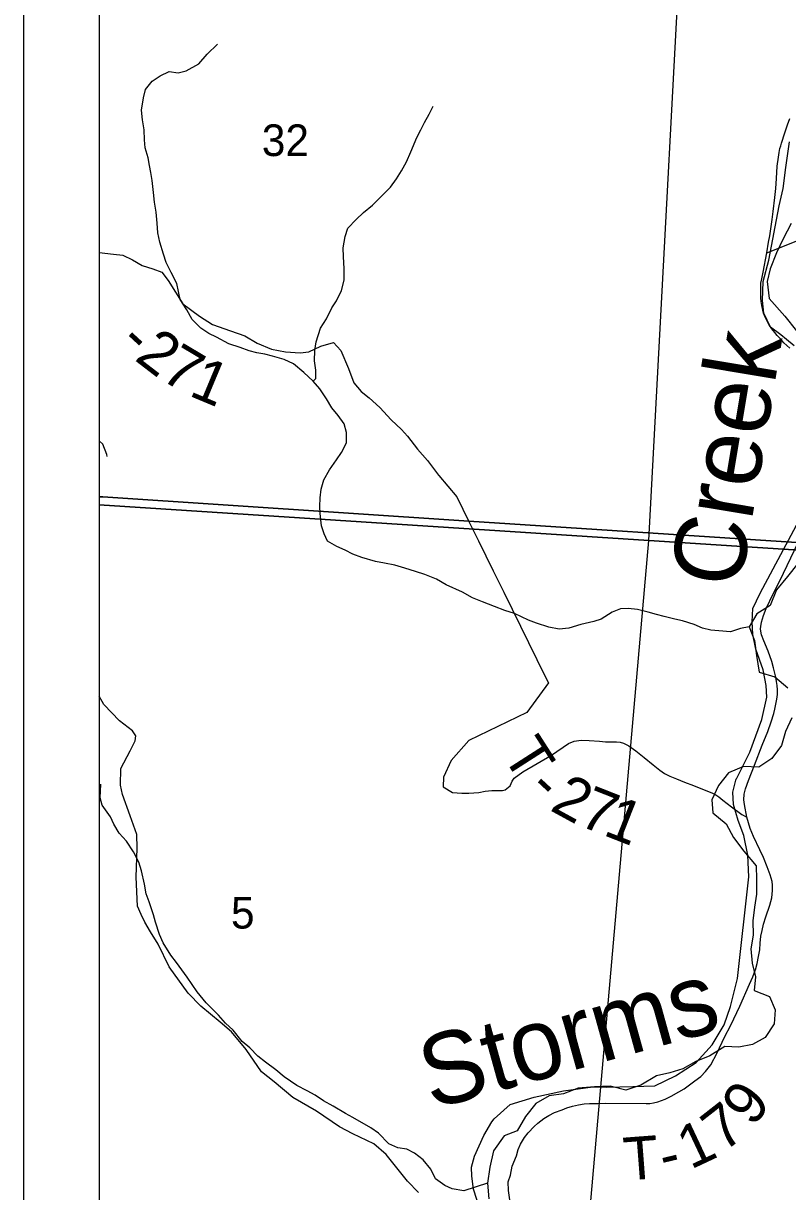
# Model space of a CAD drawing. Extents: x 0 to 34, y 0 to 22.
# Drawn here: x 2 to 3.01, y 18.721 to 20.265 of the extents above; entities that cross this region are included whole.
import ezdxf

# ---------------------------------------------------------------- set-up
doc = ezdxf.new("R2010")
doc.units = 0
for name, color, linetype in [('GM_X_Corporation', 7, 'Continuous'), ('GM_X_County_Road', 7, 'Continuous'), ('GM_X_Minor_River', 7, 'Continuous'), ('GM_X_Minor_River_Text', 7, 'Continuous'), ('GM_X_Rail_Line', 7, 'Continuous'), ('GM_X_Section_Text', 7, 'Continuous'), ('GM_X_Township_Road', 7, 'Continuous'), ('GM_X_Township_Road_Text', 7, 'Continuous'), ('SH_Data', 7, 'Continuous')]:
    doc.layers.add(name, color=color, linetype=linetype)

msp = doc.modelspace()

# ---------------------------------------------------------------- linework, layer by layer
at = {"layer": 'GM_X_Corporation'}
for points in [[(3.3441, 14.1), (8.9, 14.1), (8.9, 20.9), (2.1, 20.9), (2.1, 16.1353), (2.1457, 16.065), (2.3447, 15.6926), (2.4297, 15.5215), (2.465, 15.4504), (2.4884, 15.4033), (2.5769, 15.2135), (2.7849, 14.8403), (2.8931, 14.6544), (3.0297, 14.4867), (3.1386, 14.3654), (3.228, 14.2415)], [(6.9348, 20.9), (2.1, 20.9), (2.1, 19.6396), (2.105, 19.6393), (2.5886, 19.6074), (3.0215, 19.5789), (3.8201, 19.5262), (3.8692, 19.5228), (4.8375, 19.4557), (5.0201, 19.4401), (5.6539, 19.3859), (5.9419, 19.3649), (6.5423, 19.3229), (6.824, 19.3005), (6.835, 19.4037), (6.8961, 20.3303), (6.9032, 20.4198)], [(2.1, 20.6488), (2.1, 19.629), (2.8266, 19.5815), (2.8805, 20.5967)], [(3.8795, 20.5363), (3.8179, 19.5177), (2.8266, 19.5815), (2.8805, 20.5967)], [(2.1, 19.629), (2.1, 18.5966), (2.7366, 18.558), (2.8266, 19.5815)], [(2.8266, 19.5815), (3.8179, 19.5177), (3.742, 18.4953), (2.7366, 18.558)]]:
    msp.add_lwpolyline(points, close=True, dxfattribs=at)
msp.add_lwpolyline([(6.7043, 17.4985), (6.7536, 18.2991), (6.7629, 18.3924), (6.7876, 18.7583), (6.824, 19.3005), (6.5423, 19.3229), (5.9419, 19.3649), (5.6539, 19.3859), (5.0201, 19.4401), (4.8375, 19.4557), (3.8692, 19.5228), (3.8201, 19.5262), (3.0215, 19.5789), (2.5886, 19.6074), (2.105, 19.6393), (2.1, 19.6396), (2.1, 16.1353)], dxfattribs=at)
at = {"layer": 'GM_X_County_Road'}
for points in [[(2.1107, 19.6926), (2.1105, 19.6955), (2.1049, 19.7092), (2.1, 19.7134)], [(2.5221, 18.7197), (2.5078, 18.7347), (2.4796, 18.7702), (2.4633, 18.7839), (2.4354, 18.7974), (2.4176, 18.8066), (2.3874, 18.8273), (2.356, 18.8454), (2.3315, 18.866), (2.3145, 18.8794), (2.2942, 18.9088), (2.2751, 18.9321), (2.26, 18.9451), (2.2343, 18.9662), (2.2177, 18.9834), (2.1926, 19.0181), (2.178, 19.0482), (2.1682, 19.0642), (2.1607, 19.0772), (2.1555, 19.0871), (2.1506, 19.0985), (2.149, 19.1365), (2.1503, 19.1749), (2.1501, 19.1931), (2.1411, 19.2178), (2.1311, 19.246), (2.1285, 19.2582), (2.129, 19.2802), (2.1409, 19.3037), (2.1479, 19.3169), (2.1487, 19.3234), (2.1441, 19.3299), (2.1268, 19.3433), (2.1061, 19.365), (2.1, 19.3757)]]:
    msp.add_lwpolyline(points, dxfattribs=at)
at = {"layer": 'GM_X_Minor_River'}
for points in [[(2.2045, 20.2001), (2.2151, 20.2024), (2.2317, 20.2119), (2.2427, 20.2244), (2.2566, 20.2377)], [(2.959, 19.4675), (2.9475, 19.4655), (2.9343, 19.461), (2.9191, 19.4621), (2.9082, 19.4632), (2.8972, 19.4659), (2.8863, 19.4708), (2.8711, 19.4757), (2.8609, 19.4776), (2.8469, 19.481), (2.8364, 19.484), (2.8254, 19.4871), (2.8114, 19.4905), (2.7993, 19.492), (2.7891, 19.4912), (2.7781, 19.487), (2.7634, 19.4779), (2.7536, 19.4745), (2.7366, 19.4707), (2.7207, 19.4658), (2.7082, 19.4646), (2.6942, 19.4669), (2.678, 19.4726), (2.6674, 19.4763), (2.6489, 19.4851), (2.6364, 19.4892), (2.6224, 19.4945), (2.6069, 19.5006), (2.5933, 19.5059), (2.5801, 19.5135), (2.5585, 19.5229), (2.5461, 19.5305), (2.5306, 19.5366), (2.5181, 19.5407), (2.5041, 19.5449), (2.4909, 19.5491), (2.4773, 19.5517), (2.4655, 19.554), (2.4474, 19.5593), (2.4353, 19.5638), (2.4251, 19.5687), (2.4141, 19.5737), (2.402, 19.5809), (2.3975, 19.5907), (2.3941, 19.601), (2.3922, 19.6173), (2.3918, 19.6268), (2.3922, 19.6381), (2.3937, 19.6495), (2.3971, 19.6617), (2.4047, 19.6753), (2.4138, 19.6882), (2.4202, 19.6981), (2.427, 19.7106), (2.427, 19.7243), (2.424, 19.736), (2.4161, 19.747), (2.4078, 19.7572), (2.4006, 19.769), (2.3919, 19.7823), (2.3828, 19.7925), (2.3707, 19.8039), (2.3571, 19.8152), (2.3446, 19.8209), (2.3291, 19.8255), (2.3189, 19.8281), (2.3083, 19.8296), (2.2985, 19.8323), (2.2864, 19.8368), (2.2713, 19.8417), (2.2551, 19.8505), (2.2452, 19.8554), (2.2346, 19.8626), (2.2229, 19.874), (2.2161, 19.8865), (2.2071, 19.9005), (2.2029, 19.9214), (2.1953, 19.9358), (2.1889, 19.9494), (2.1851, 19.96), (2.1802, 19.9763), (2.1776, 19.9885), (2.1768, 20.001), (2.1753, 20.0158), (2.1734, 20.0291), (2.1719, 20.0416), (2.17, 20.0575), (2.1685, 20.0681), (2.1666, 20.0776), (2.1648, 20.0875), (2.161, 20.1007), (2.1602, 20.1113), (2.1595, 20.1246), (2.1576, 20.1379), (2.1561, 20.1508), (2.1587, 20.1671), (2.1614, 20.1777), (2.1704, 20.1887), (2.1807, 20.1959), (2.1928, 20.2016), (2.2045, 20.2001)], [(2.3828, 19.7925), (2.3866, 19.7959), (2.3866, 19.8069), (2.3847, 19.8194), (2.3851, 19.8327), (2.387, 19.8445), (2.3927, 19.8623), (2.4006, 19.8748), (2.4078, 19.8892), (2.4138, 19.8987), (2.4203, 19.9124), (2.424, 19.926), (2.4237, 19.9412), (2.4229, 19.9568), (2.4225, 19.9685), (2.4252, 19.9837), (2.4286, 19.9947), (2.4396, 20.0061), (2.4494, 20.0152), (2.4615, 20.0251), (2.4853, 20.049), (2.4932, 20.0596), (2.4997, 20.0706), (2.5061, 20.0824), (2.5118, 20.0956), (2.5197, 20.1146), (2.525, 20.1245), (2.5299, 20.1343), (2.5364, 20.1453), (2.5417, 20.156)], [(3.0147, 20.0007), (3.0041, 19.9806), (2.9953, 19.9619), (2.987, 19.941), (2.9828, 19.9239), (2.9857, 19.9015), (3.0061, 19.8783), (3.0216, 19.8588)], [(3.0235, 19.5512), (3.0099, 19.5341), (2.9954, 19.5166), (2.9867, 19.4957), (2.9692, 19.4847), (2.959, 19.4675), (2.9661, 19.4497), (2.9687, 19.4295), (2.9721, 19.4078), (2.9929, 19.4013), (3.0103, 19.3869)], [(3.0155, 19.3473), (3.0071, 19.3294), (3.0018, 19.3108), (2.9889, 19.2933), (2.9718, 19.2819), (2.9517, 19.2831), (2.9317, 19.2747), (2.9187, 19.2576), (2.9096, 19.239), (2.9111, 19.2215), (2.9285, 19.207), (2.9383, 19.1891), (2.9519, 19.1709), (2.9685, 19.1518), (2.9688, 19.134), (2.9688, 19.1142), (2.9661, 19.0971), (2.9638, 19.0788), (2.9645, 19.0598), (2.9614, 19.0419), (2.9632, 19.0229), (2.9674, 19.005), (2.9658, 18.9867), (2.9859, 18.9787), (2.9934, 18.9612), (2.9922, 18.9426), (2.9804, 18.9247)], [(2.6132, 18.7321), (2.5822, 18.722), (2.5667, 18.7247), (2.5568, 18.7292), (2.5448, 18.738), (2.5383, 18.7505), (2.5285, 18.763), (2.5168, 18.7717), (2.5066, 18.777), (2.4949, 18.7789), (2.4828, 18.7842), (2.4692, 18.7982), (2.4593, 18.8054), (2.4355, 18.8187), (2.4257, 18.824), (2.4094, 18.8339), (2.3966, 18.8411), (2.3856, 18.8483), (2.3751, 18.8543), (2.3614, 18.8612), (2.3448, 18.8725), (2.3335, 18.882), (2.3199, 18.8919), (2.31, 18.8998), (2.2991, 18.9108), (2.2893, 18.9192), (2.2772, 18.9343), (2.2673, 18.9438), (2.2579, 18.9544), (2.2416, 18.9707), (2.2295, 18.9852), (2.2163, 19.0045), (2.2023, 19.0238), (2.1948, 19.0337), (2.1846, 19.05), (2.1797, 19.061), (2.1744, 19.0773), (2.1721, 19.0868), (2.1661, 19.1042), (2.1623, 19.1145), (2.16, 19.1274), (2.1562, 19.1448), (2.1525, 19.1566), (2.1453, 19.1699), (2.1362, 19.1843), (2.1264, 19.1949), (2.1196, 19.2067), (2.1151, 19.2165), (2.1041, 19.2317), (2.1015, 19.2415), (2.1022, 19.2594)], [(2.9804, 18.9247), (2.9634, 18.9152), (2.9456, 18.9118), (2.927, 18.9126), (2.9073, 18.9004), (2.8884, 18.8928), (2.8713, 18.8833), (2.8543, 18.878), (2.8368, 18.8742), (2.816, 18.8617), (2.7963, 18.8549), (2.7755, 18.8602), (2.7547, 18.8595), (2.7331, 18.8576), (2.7138, 18.8504), (2.6948, 18.8477), (2.677, 18.8375), (2.6633, 18.8203), (2.6523, 18.8013), (2.6353, 18.7945), (2.6212, 18.7747), (2.6166, 18.7534), (2.6132, 18.7321), (2.615, 18.7116)]]:
    msp.add_lwpolyline(points, dxfattribs=at)
at = {"layer": 'GM_X_Rail_Line'}
for points in [[(3.0185, 19.8389), (3.0085, 19.8476), (3.0009, 19.8537), (2.9873, 19.8639), (2.9785, 19.8824), (2.9769, 19.8989), (2.9777, 19.9242), (2.9849, 19.9524), (2.9986, 20.024), (3.0042, 20.0469), (3.0073, 20.0748), (3.0122, 20.1085)], [(2.6037, 18.697), (2.5949, 18.7243), (2.5928, 18.7415), (2.5922, 18.7534), (2.5963, 18.7678), (2.6085, 18.7949), (2.6192, 18.813), (2.622, 18.8173), (2.6431, 18.8359), (2.6751, 18.8459), (2.7137, 18.8542), (2.7524, 18.8593), (2.7708, 18.8588), (2.8053, 18.8598), (2.8345, 18.8609), (2.8618, 18.8738), (2.8892, 18.8915), (2.9101, 18.9149), (2.9262, 18.9414), (2.9342, 18.9656), (2.9435, 19.0028), (2.9587, 19.1369), (2.9573, 19.1659), (2.9522, 19.1918), (2.9444, 19.2115), (2.9382, 19.2329), (2.9377, 19.2488), (2.9417, 19.2665), (2.9423, 19.2667), (2.9599, 19.3018), (2.9759, 19.345), (2.9825, 19.3745), (2.9817, 19.3898), (2.9777, 19.4108), (2.968, 19.4381), (2.964, 19.4574), (2.9632, 19.4743), (2.964, 19.492), (2.9736, 19.5122), (3.0452, 19.6466)]]:
    msp.add_lwpolyline(points, dxfattribs=at)
at = {"layer": 'GM_X_Township_Road'}
msp.add_line((2.6349, 19.5133), (2.6897, 19.4018), dxfattribs=at)
for points in [[(3.0126, 19.836), (3.005, 19.8431), (3.0004, 19.8482), (2.9961, 19.8526), (2.9928, 19.8565), (2.989, 19.8613), (2.986, 19.8658), (2.9831, 19.8707), (2.98, 19.8769), (2.9779, 19.8824), (2.9756, 19.8922), (2.9748, 19.8975), (2.9745, 19.9027), (2.9743, 19.9064), (2.9743, 19.9103), (2.9743, 19.915), (2.9747, 19.9217), (2.9756, 19.9276), (2.9774, 19.9366), (2.9823, 19.9621), (2.9848, 19.9762), (2.9862, 19.9845), (2.9893, 20.0059), (2.9908, 20.0167), (2.9929, 20.0351), (2.9942, 20.0469), (2.9951, 20.0602), (2.9962, 20.0764), (2.9977, 20.0886), (2.9986, 20.0948), (2.9998, 20.0997), (3.0007, 20.1034), (3.0017, 20.1071), (3.006, 20.1205), (3.0098, 20.1312), (3.0129, 20.1395)], [(2.9823, 19.9621), (3.107, 20.0118), (3.2438, 20.0434), (3.2996, 20.0612), (3.3426, 20.0749), (3.3797, 20.0723), (3.3816, 20.0722)], [(2.1, 19.9623), (2.1191, 19.9604), (2.1313, 19.9589), (2.144, 19.9527), (2.157, 19.9451), (2.1712, 19.9409), (2.1831, 19.9366), (2.1915, 19.9255), (2.2108, 19.8946), (2.2327, 19.8781), (2.2497, 19.8674), (2.2739, 19.8589), (2.2928, 19.8523), (2.3091, 19.8424), (2.328, 19.8347), (2.3465, 19.8311), (2.3659, 19.8299), (2.3772, 19.8313), (2.3932, 19.8388), (2.4099, 19.8436), (2.4197, 19.833), (2.4298, 19.809), (2.4365, 19.7903), (2.4463, 19.7785), (2.4569, 19.7704), (2.4712, 19.7574), (2.4859, 19.741), (2.4998, 19.7284), (2.5077, 19.7196), (2.5209, 19.7025), (2.5341, 19.6876), (2.5484, 19.6681), (2.549, 19.6674), (2.5728, 19.6395), (2.5888, 19.6069), (2.6014, 19.5813), (2.6209, 19.5417), (2.6349, 19.5133)], [(3.0095, 19.5488), (3.0234, 19.5783)], [(2.6427, 18.7102), (2.6409, 18.7224), (2.6407, 18.734), (2.6436, 18.7428), (2.6459, 18.7544), (2.6515, 18.7684), (2.6538, 18.7764), (2.6568, 18.7838), (2.6623, 18.7926), (2.6671, 18.7985), (2.6748, 18.8069), (2.68, 18.8116), (2.6876, 18.8174), (2.6944, 18.8215), (2.7017, 18.8254), (2.7118, 18.8292), (2.7181, 18.8315), (2.7255, 18.8338), (2.7335, 18.8356), (2.7412, 18.8368), (2.7479, 18.8374), (2.7591, 18.8376), (2.7692, 18.8377), (2.8229, 18.8373), (2.8277, 18.8375), (2.8325, 18.8384), (2.8384, 18.8397), (2.8479, 18.8431), (2.8558, 18.8473), (2.866, 18.8529), (2.8731, 18.8569), (2.8872, 18.8672), (2.8952, 18.8732), (2.9014, 18.8798), (2.9084, 18.8887), (2.9166, 18.9042), (2.9266, 18.925), (2.9348, 18.941), (2.9467, 18.9661), (2.9597, 18.9952), (2.9638, 19.0048), (2.9671, 19.0133), (2.9674, 19.0142), (2.9695, 19.0224), (2.9715, 19.0319), (2.9732, 19.0407), (2.9735, 19.0492), (2.9747, 19.0585), (2.9761, 19.0662), (2.9779, 19.0746), (2.9813, 19.0843), (2.9864, 19.0997), (2.9891, 19.1092), (2.99, 19.1188), (2.9901, 19.126), (2.9894, 19.1311), (2.9867, 19.1396), (2.9827, 19.1505), (2.9778, 19.1624), (2.9733, 19.1729), (2.965, 19.1903), (2.9606, 19.201), (2.9559, 19.2158), (2.953, 19.2325), (2.9522, 19.239), (2.9523, 19.2462), (2.9543, 19.2536), (2.958, 19.2643), (2.966, 19.2847), (2.9762, 19.3111), (2.9837, 19.3292), (2.9883, 19.342), (2.9915, 19.353), (2.9929, 19.3585), (2.9945, 19.3654), (2.9956, 19.3721), (2.9965, 19.378), (2.9964, 19.3843), (2.9961, 19.39), (2.9952, 19.3952), (2.9941, 19.4008), (2.9926, 19.4079), (2.9914, 19.4134), (2.9892, 19.4216), (2.9841, 19.4354), (2.9786, 19.449), (2.9753, 19.4569), (2.9743, 19.4619), (2.9739, 19.4648), (2.9744, 19.4679), (2.9755, 19.4738), (2.9781, 19.4827), (2.9814, 19.4917), (2.9906, 19.5114), (2.9998, 19.5282), (3.0095, 19.5488)], [(2.6897, 19.4018), (2.6937, 19.3937), (2.6653, 19.3545), (2.5886, 19.3171), (2.5654, 19.2909), (2.5551, 19.269), (2.5548, 19.2559), (2.5672, 19.2485), (2.5795, 19.2478), (2.5888, 19.2478), (2.602, 19.2486), (2.6102, 19.2504), (2.6192, 19.251), (2.6303, 19.251), (2.6329, 19.2514)], [(2.6329, 19.2514), (2.6367, 19.2519), (2.6431, 19.2574), (2.6457, 19.2634), (2.6487, 19.2673), (2.6598, 19.2758), (2.6979, 19.2977), (2.7203, 19.3132), (2.7278, 19.3166), (2.737, 19.3179), (2.7478, 19.3174), (2.7613, 19.3165), (2.7693, 19.3157), (2.7837, 19.3154), (2.7884, 19.315), (2.7932, 19.3138), (2.8, 19.3104), (2.8093, 19.3037), (2.8204, 19.2948), (2.832, 19.2851), (2.8411, 19.2782), (2.8471, 19.2736), (2.8544, 19.2702), (2.8629, 19.2665), (2.8738, 19.262), (2.8853, 19.2576), (2.8998, 19.252), (2.9076, 19.249), (2.9139, 19.2462), (2.9191, 19.2428), (2.9244, 19.2384), (2.9357, 19.2296), (2.9492, 19.2195), (2.9559, 19.2158)]]:
    msp.add_lwpolyline(points, dxfattribs=at)
at = {"layer": 'SH_Data'}
for p, q in [((2, 21), (2, 14)), ((2.1, 20.9), (2.1, 14.1))]:
    msp.add_line(p, q, dxfattribs=at)

# ---------------------------------------------------------------- texts
at = {"layer": 'GM_X_Minor_River_Text'}
for s, rotation, p in [('Creek', 80.4921, (2.9472, 19.516)), ('Storms', 15.5032, (2.5392, 18.8291))]:
    msp.add_text(s, height=0.0947, rotation=rotation, dxfattribs=at).set_placement(p)
at = {"layer": 'GM_X_Section_Text'}
for s, height, p in [('32', 0.04186, (2.3151, 20.0899)), ('5', 0.0419, (2.2743, 19.0687))]:
    msp.add_text(s, height=height, rotation=0, dxfattribs=at).set_placement(p)
at = {"layer": 'GM_X_Township_Road_Text'}
for s, rotation, p in [('-', 317.1587, (2.1241, 19.8407)), ('2', 322.4255, (2.1455, 19.8211)), ('7', 329.2123, (2.1793, 19.7957)), ('1', 337.3284, (2.2172, 19.7738)), ('T', 302.6963, (2.6318, 19.2984)), ('-', 317.0271, (2.6646, 19.2507)), ('2', 331.3579, (2.6943, 19.2258)), ('7', 338.5233, (2.732, 19.2057)), ('1', 338.5233, (2.7646, 19.1929)), ('9', 52.8673, (2.964, 18.8049)), ('7', 38.0141, (2.9252, 18.7719)), ('1', 25.169, (2.8817, 18.7497)), ('T', 4.3593, (2.795, 18.7354)), ('-', 13.3938, (2.847, 18.7401))]:
    msp.add_text(s, height=0.0568, rotation=rotation, dxfattribs=at).set_placement(p)

doc.saveas('drawing.dxf')
